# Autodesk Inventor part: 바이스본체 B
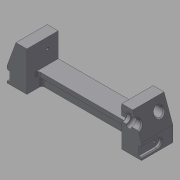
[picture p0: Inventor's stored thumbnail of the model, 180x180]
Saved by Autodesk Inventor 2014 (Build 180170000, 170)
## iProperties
Created: 2017-04
Part Number: 바이스본체 B
Material: 일반
Document SubType Name: Modeling
Designer: mduedu
Density: 1 g/cm^3
Appearance: 기본값
Author: mduedu
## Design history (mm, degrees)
sketch "스케치1"
  geometry: L1 (-75, 0)-(75, 0); L2 (-75, 0)-(-75, 17); L3 (-53, 17)-(53, 17); L4 (75, 17)-(75, 0); L5 (-75, 17)-(-65.173, 44); L6 (-65.173, 44)-(-53, 44); L7 (-53, 44)-(-53, 17); L8 (0, 0)-(0, 17); L9 (75, 17)-(65.173, 44); L10 (65.173, 44)-(53, 44); L11 (53, 44)-(53, 17); 1 further point
  constraints: 22 end point, 4 perpendicular, 2 horizontal alignment, 2 midpoint, 2 symmetric about line, 1 coincident, 1 collinear, 1 horizontal, 1 vertical
  dimensions: "d0" = 150 distance of L1.start L1.end; "d1" = 17 distance of L1.start L2.end; "d2" = 27 distance of L3.start L6.end; "d3" = 22 distance of L3.start L2.end; "d4" = 70 deg angle of L3 L5; "d54" = 20 deg angle of L9 L4
extrude "돌출1" new body sketch "스케치1" stored distance "d5" = 70; taper "d6" = 0 deg
sketch "스케치2"
  geometry: L1 (0, 70)-(106, 70) reference; L2 (106, 70)-(106, 0) reference; L3 (106, 0)-(0, 0) reference; L4 (0, 47)-(106, 47); L5 (106, 47)-(106, 23); L6 (106, 23)-(0, 23); L7 (0, 23)-(0, 47); L8 (0, 70)-(0, 0) reference; 2 further points
  constraints: 8 end point, 2 parallel, 2 point on line, 1 horizontal, 1 horizontal alignment, 1 midpoint, 1 perpendicular
  dimensions: "d7" = 24 distance between parallel lines of L6 L4
extrude "돌출2" cut sketch "스케치2" stored distance "d9" = 70; taper "d10" = 0 deg
sketch "스케치3"
  geometry: L1 (22, -23)-(128, -23) reference; L2 (128, -47)-(22, -47) reference; L3 (22, -18)-(128, -18); L4 (128, -52)-(22, -52); L5 (22, -18)-(22, -52); L6 (128, -18)-(128, -52); 1 further point
  constraints: 8 end point, 3 parallel, 2 point on line, 1 perpendicular
  dimensions: "d11" = 5 distance between parallel lines of L3 L1; "d12" = 5 distance between parallel lines of L4 L2
extrude "돌출3" cut sketch "스케치3" distance "d13" = 12; taper "d14" = 0 deg
fillet "모깎기1" dims "d15" = 3, "d16" = 3
sketch "스케치4"
  geometry: L1 (103, 23)-(3, 23) reference; L2 (0, 26)-(0, 0) reference; L3 (106, 0)-(0, 0) reference; L4 (106, 26)-(106, 0) reference; L5 (96, 0)-(90, 0); L6 (90, 0)-(90, 19.5); L7 (96, 19.5)-(96, 0); L8 (90, 19.5)-(96, 19.5); A1 r 3 centre (3, 26) between (0, 26) and (3, 23) reference; A2 r 3 centre (103, 26) between (103, 23) and (106, 26) reference; 1 further point
  constraints: 8 end point, 2 perpendicular, 1 horizontal, 1 parallel, 1 point on line
  dimensions: "d17" = 10 distance between parallel lines of L7 L4; "d18" = 6 distance between parallel lines of L7 L6; "d27" = 3.5 distance between parallel lines of L8 L1
extrude "돌출4" join sketch "스케치4" distance "d19" = 12; taper "d20" = 0 deg
chamfer "모따기1" distance "d21" = 3; stored, may be unused: second distance "d22" = 2, angle "d23" = 45 deg
chamfer "모따기2" distance "d24" = 3; stored, may be unused: second distance "d25" = 2, angle "d26" = 45 deg
sketch "스케치5"
  geometry: L1 (-15.5, 35.8)-(-15.5, -25.8) reference; L2 (19.5, 0)-(0, 0) reference; C1 r 6.5 at (9.5, 15); 1 further point
  constraints: 1 centre point
  dimensions: "d28" = 13 diameter of C1; "d30" = 15 distance from line of C1.centre L2; "d31" = 25 distance from line of C1.centre L1
extrude "돌출5" cut sketch "스케치5" stored distance "d32" = 12; taper "d33" = 0 deg
sketch "스케치6"
  geometry: C1 r 5 at (-10, 15); C2 r 5 at (-60, 15); A1 r 6.5 centre (-10, 15) between (-15.766, 12) and (-4.234, 12) reference; A2 r 6.5 centre (-60, 15) between (-65.766, 12) and (-54.234, 12) reference; 1 further point
  constraints: 2 centre point, 2 coincident
  dimensions: "d34" = 10 diameter of C1; "d35" = 10 diameter of C2 (= d34)
extrude "돌출6" cut sketch "스케치6" stored distance "d36" = 12; taper "d37" = 0 deg
chamfer "모따기3" distance "d38" = 1; stored, may be unused: second distance "d39" = 2, angle "d40" = 45 deg
chamfer "모따기4" distance "d41" = 1; stored, may be unused: second distance "d42" = 2, angle "d43" = 45 deg
sketch "스케치7"
  geometry: L1 (-35, 35.8)-(-35, -25.8) reference; L2 (-70, 0)-(0, 0) reference; C1 r 5 at (-35, 15); 1 further point
  constraints: 1 centre point, 1 point on line
  dimensions: "d44" = 10 diameter of C1; "d45" = 15 distance from line of C1.centre L2
extrude "돌출7" cut sketch "스케치7" stored distance "d46" = 12; taper "d47" = 0 deg
chamfer "모따기5" distance "d48" = 1; stored, may be unused: second distance "d49" = 2, angle "d50" = 45 deg
node "작업축1"
sketch "스케치8"
  geometry: L1 (-105, 32)-(105, 32) reference; L2 (58, 32)-(64, 32); L3 (64, 32)-(64, 40); L4 (64, 40)-(58, 40); L5 (58, 40)-(58, 32); L6 (53, 38)-(53, 26) reference; 1 further point
  constraints: 8 end point, 2 parallel, 1 horizontal, 1 perpendicular, 1 point on line
  dimensions: "d51" = 5 distance from line of L6 L2.start; "d52" = 6 distance of L3.end L4.end; "d53" = 16 diameter of L4 L1
revolve "회전1" sketch "스케치8" stored, may be unused: angle "d55" = 90 deg
fillet "모깎기2"
chamfer "모따기6" distance "d56" = 1; stored, may be unused: second distance "d57" = 2, angle "d58" = 45 deg
sketch "스케치9"
  geometry: L1 (17.5, 3)-(52.5, 3); L2 (52.5, 13)-(17.5, 13); L3 (70, 0)-(0, 0) reference; L4 (17.5, 8)-(52.5, 8); A1 r 5 centre (17.5, 8) between (17.5, 13) and (17.5, 3); A2 r 5 centre (52.5, 8) between (52.5, 3) and (52.5, 13); 3 further points
  constraints: 6 end point, 4 point on circle, 3 tangent, 2 centre point, 2 midpoint, 2 parallel, 1 horizontal, 1 vertical alignment
  dimensions: "d59" = 35 distance of L4.start L4.end; "d61" = 5 radius of A2; "d62" = 8 distance between parallel lines of L3 L4
extrude "돌출8" cut sketch "스케치9" distance "d63" = 3; taper "d64" = 0 deg
chamfer "모따기7" distance "d65" = 1; stored, may be unused: second distance "d66" = 2, angle "d67" = 45 deg
chamfer "모따기8" distance "d68" = 1; stored, may be unused: second distance "d69" = 2, angle "d70" = 45 deg
feature "분할1"
sketch "스케치10"
  geometry: A1 r 5 centre (0, 0) between (0, 5) and (0, -5) reference; 1 further point
  constraints: 1 coincident
hole "구멍1" sketch "스케치10" at (0, 0) diameter "d71" = 2.459; stored, may be unused: countersink angle "d75" = 90 deg, drill point angle "d77" = 120 deg; dims "d72" = 4.5, "d73" = 4, "d74" = 2, "d76" = 6
sketch "스케치11"
  geometry: L1 (0, 0)-(0, 27) reference; L2 (0, 27)-(-35, 27) reference; 2 further points
  dimensions: "d78" = 12 distance from line of point (-12, 15.5) L1; "d79" = 11.5 distance from line of point (-12, 15.5) L2
hole "구멍2" sketch "스케치11" at (-12, 15.5) diameter "d80" = 3.242; stored, may be unused: countersink angle "d84" = 90 deg, drill point angle "d86" = 120 deg; dims "d81" = 6, "d82" = 4, "d83" = 2, "d85" = 8
node "솔리드1"
mirror "대칭1"
mirror "대칭2"
mirror "대칭3"
mirror "대칭4"
node "투영된 루프1"
